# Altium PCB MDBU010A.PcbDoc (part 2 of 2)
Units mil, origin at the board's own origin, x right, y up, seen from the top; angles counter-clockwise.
Board outline 3300 x 2500 mil, 2 copper layers (Top Layer, Bottom Layer), stack 64.8 mil thick; 105 components, 70 nets, 307 pads, 460 vias.
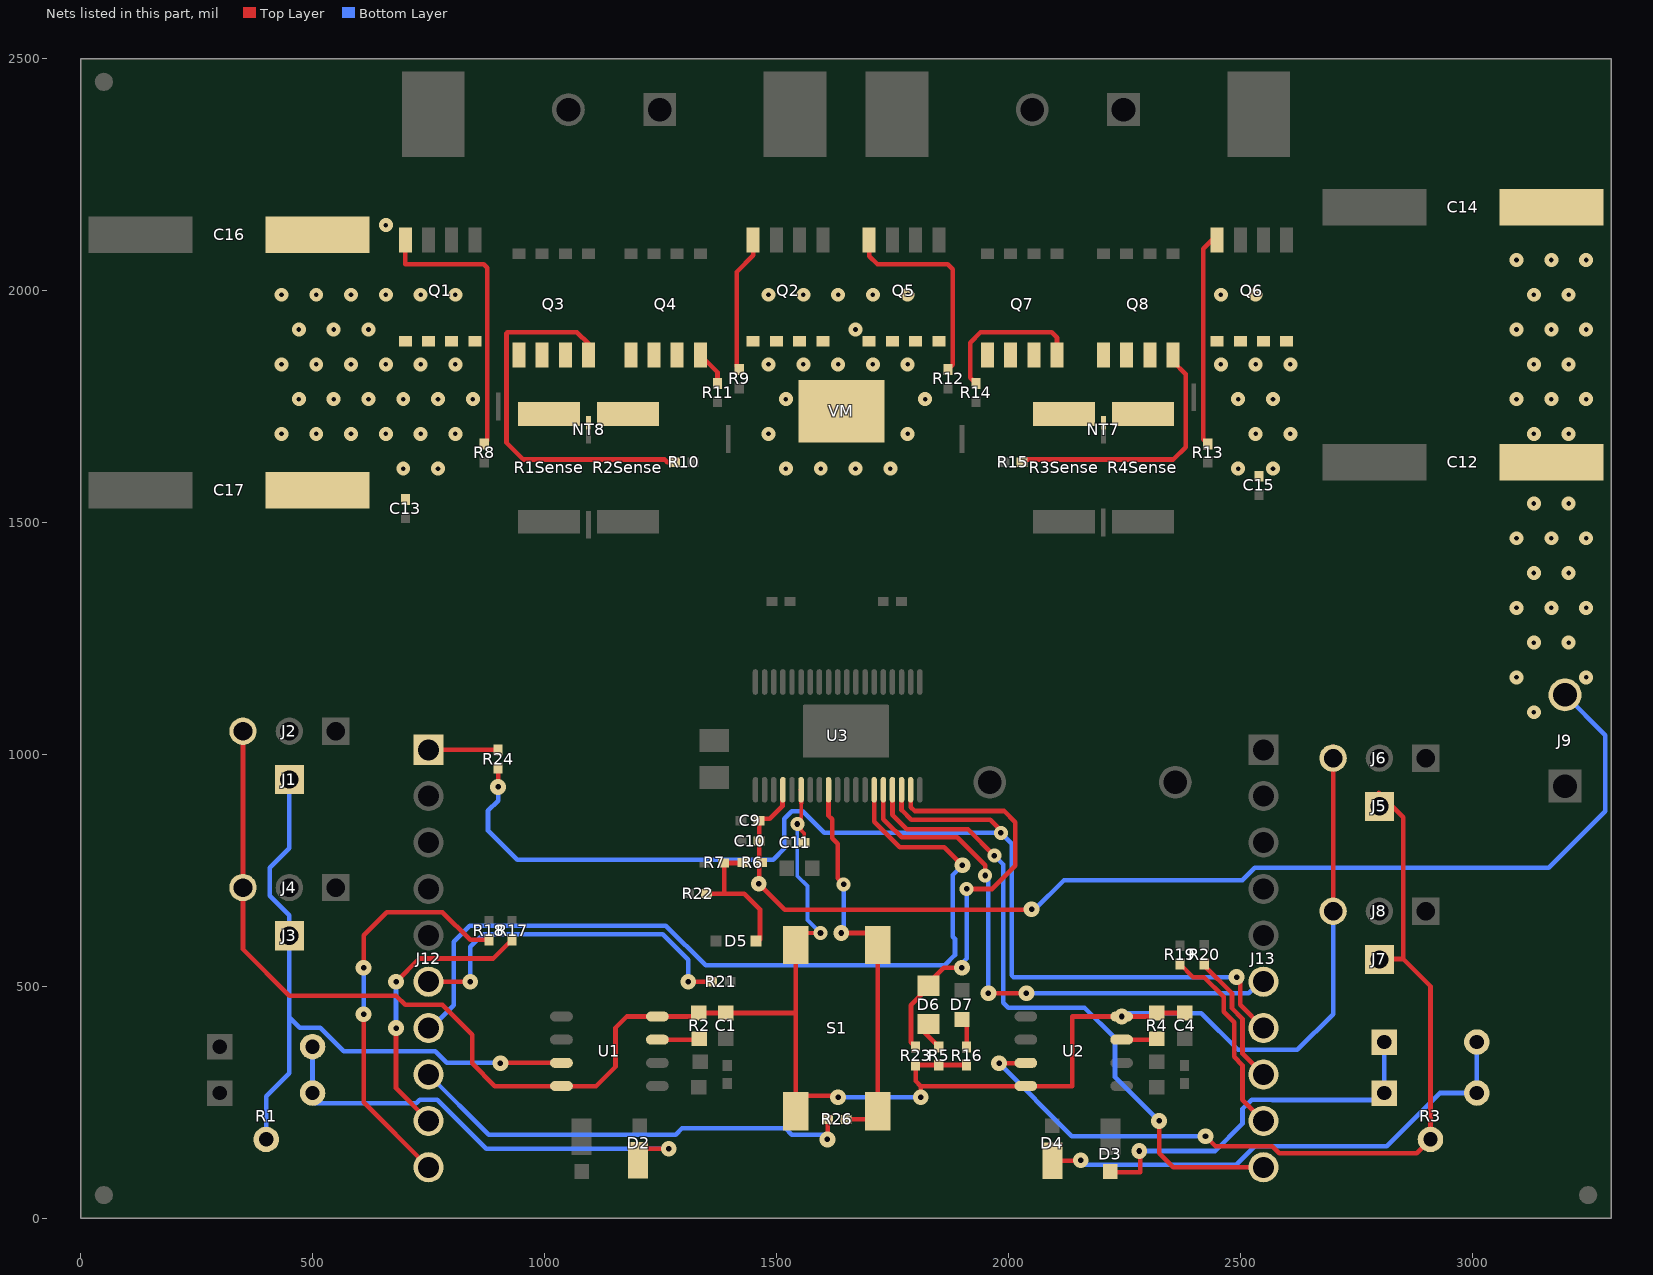
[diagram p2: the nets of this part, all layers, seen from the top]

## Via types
v1: diameter 30, hole 10, Top Layer to Bottom Layer, tented both sides, 357 vias
v2: diameter 34, hole 12, Top Layer to Bottom Layer, 60 vias
v3: diameter 34, hole 12, Top Layer to Bottom Layer, tented top, 20 vias
v4: diameter 20, hole 8, Top Layer to Bottom Layer, 12 vias
v5: diameter 30, hole 12, Top Layer to Bottom Layer, 11 vias

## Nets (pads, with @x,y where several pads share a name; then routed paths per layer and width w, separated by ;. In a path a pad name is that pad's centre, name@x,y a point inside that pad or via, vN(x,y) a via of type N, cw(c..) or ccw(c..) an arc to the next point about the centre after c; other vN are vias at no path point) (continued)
NetD2_1: D2.1 pad.1@500,370 R1.3 | length 978.7
  Top Layer w10: D2.1@1200,150 v2(1268,150)
  Bottom Layer w10: R1.3@500,270 pad.1@500,370 ; R1.3@504,248 723.86,248 731.21,255.35 768.79,255.35 874.14,150 v2(1268,150)
NetD3_2: D3.2 pad.0@2810,380 R3.1 | length 797.4
  Top Layer w10: D3.2@2220,100.79 2220,99 2284,99 v2@2284,143
  Bottom Layer w10: v2(2282,145) 2446,145 2504.65,203.65 2504.65,235.65 2524.35,255.35 2568.79,255.35 2569.14,255 R3.1@2795,255 ; R3.1@2810,270 pad.0@2810,380
NetD4_1: D4.1 pad.1@3010,380 R3.3 | length 1099.6
  Top Layer w10: D4.1@2095,124.41 2156,124.41 v2(2156,125)
  Bottom Layer w10: v2(2156,125) 2156,115.13 2490.99,115.13 2531.21,155.35 2815.35,155.35 2930,270 R3.3@3010,270 pad.1@3010,380
NetD5_1: D5.1 R6.1 R7.2 R22.2 | length 301.8
  Top Layer w10: R22.2@1349.69,700 1387.65,700 ; R6.1@1429.28,766 1387.65,766 1387.65,700 ; D5.1@1464.47,601 1464.47,666.56 1431.03,700 1387.65,700
NetD6_1: D6.1 R23.1 U3.18 | length 911.8
  Top Layer w10: U3.18@1789.48,923.86 1789.48,886.52 1798,878 1991,878 2015,854 2015,760 1965,710 v5(1910,710) ; R23.1@1800,369.68 1790,379.68 1790,459.53 D6.1@1820,489.53 ; D6.1@1815,494.53 1860.47,540 v2(1900,540)
  Bottom Layer w10: v2(1900,540) 1900,550 1910,560 v5(1910,710) v5@1909,709
NetD6_2: D6.2 R5.2 | length 73.2
  Top Layer w10: D6.2@1820,430.47 1820,399.69 R5.2@1850,369.69
NetD7_2: D7.2 R16.1 | length 48.8
  Top Layer w10: R16.1@1910,369.68 D7.2@1910,418.5
NetJ12_6: J12.6 R21.1 | length 767
  Top Layer w10: J12.6@750,510 v3(840,510) ; v2(1310,510) R21.1@1360.32,510
  Bottom Layer w10: v3(840,510) 840,584.94 867.71,612.64 1254.8,612.64 1310,557.44 v2(1310,510)
NetJ12_8: J12.8 R26.1 | length 958.1
  Top Layer w10: v2@1610.31,180.31 R26.1@1610.31,213.14
  Bottom Layer w10: J12.8@750,310 879.69,180.31 1282.89,180.31 1296.45,193.87 1519.55,193.87 1533.11,180.31 v2@1610.31,180.31
  other v2: 1610,170
NetJ12_9: J12.9 R17.1 | length 616.4
  Top Layer w10: v2(680,410) 680,280 J12.9@750,210 ; v2(680,510) 730,560 889.68,560 R17.1@930,600.32
  Bottom Layer w10: v2(680,410) v2(680,510)
NetJ12_10: J12.10 R18.1 | length 873.4
  Top Layer w10: v2(610,440) 610,250 J12.10@750,110 ; v2(610,540) 610,610 660,660 780,660 839.68,600.32 R18.1@880,600.32
  Bottom Layer w10: v2(610,440) v2(610,540)
NetJ13_8: J13.8 R20.1 | length 291.4
  Top Layer w10: R20.1@2422.28,548.49 2422.28,544.84 2482.13,485 2482.13,452.6 2504.65,430.08 2504.65,355.35 J13.8@2550,310
NetJ13_9: J13.9 R19.1 | length 426.6
  Top Layer w10: R19.1@2370,548.13 2398.13,520 2421.85,520 2464.25,477.6 2464.25,445.19 2486.77,422.67 2486.77,347.95 2504.65,330.08 2504.65,255.35 J13.9@2550,210
NetNT7_2: NT7.2 Q7.1 Q7.2 Q7.3 Q8.1 Q8.2 Q8.3 R3Sense.2 R4Sense.2
NetNT8_2: NT8.2 Q3.1 Q3.2 Q3.3 Q4.1 Q4.2 Q4.3 R1Sense.2 R2Sense.2
NetQ1_4: Q1.4 R8.2 | length 614.9
  Top Layer w10: Q1.4@700,2109.3 700,2056.43 869.31,2056.43 876.85,2048.89 876.85,1676.54 R8.2@870,1669.69
NetQ2_4: Q2.4 R9.1 | length 288.7
  Top Layer w10: R9.1@1414.26,1835.42 1414.26,2040 1450,2075.74 Q2.4@1450,2109.3
NetQ3_4: Q3.4 R10.2 | length 828.1
  Top Layer w10: Q3.4@1095,1860.7 1095,1885 1070,1910 920,1910 918.15,1908.15 918.15,1671.85 954.25,1635.75 1258.82,1635.75 1264.57,1630 R10.2@1280.31,1630
NetQ4_4: Q4.4 R11.1 | length 76.3
  Top Layer w10: Q4.4@1336,1860.7 1373,1823.7 R11.1@1373,1799.68
NetQ5_4: Q5.4 R12.2 | length 447
  Top Layer w10: Q5.4@1700,2109.3 1700,2074.3 1717.87,2056.43 1869.31,2056.43 1880,2045.74 1880,1839.69 R12.2@1870,1829.69
NetQ6_4: Q6.4 R13.1 | length 462.5
  Top Layer w10: R13.1@2430,1669.68 2420,1679.68 2420,2090 2439.3,2109.3 Q6.4@2450,2109.3
NetQ7_4: Q7.4 R14.2 | length 332.1
  Top Layer w10: R14.2@1930,1799.69 1917.87,1811.81 1917.87,1887.87 1940,1910 2093.57,1910 2105,1898.57 Q7.4@2105,1860.7
NetQ8_4: Q8.4 R15.1 | length 575.6
  Top Layer w10: R15.1@2029.68,1630 2035.43,1635.75 2355.75,1635.75 2382.13,1662.13 2382.13,1820 2355,1847.13 Q8.4@2355,1860.7
NetR2_1: R2.1 U1.7 | length 90
  Top Layer w10: U1.7@1243.35,385 R2.1@1333.32,385
NetR4_1: R4.1 U2.7 | length 73.2
  Top Layer w10: U2.7@2244.35,385 R4.1@2317.56,385
RESET: R26.2 S1.3 S1.4 U3.9 | length 793.6
  Top Layer w10: U3.9@1612.31,923.86 1612.31,867.79 1620.12,859.98 1620.12,819.23 1631.93,807.42 1631.93,733.07 v5(1645,720) ; v2(1640,615) 1710.43,615 1718.58,606.85 S1.4@1718.58,589.13 S1.3@1718.58,270.87 ; R26.2@1649.68,213.14 S1.3@1700.86,213.14
  Bottom Layer w10: v2(1640,615) 1645,620 v5(1645,720)
SCLK: J12.7 U3.14 | length 1853.6
  Top Layer w10: U3.14@1710.74,923.86 1710.74,855 1721.3,844.44 ; 1721.3,844.42 1765.72,800 1862,800 v2(1901,761)
  Bottom Layer w10: J12.7@750,410 755,410 804,459 804,596 839,631 1261.72,631 1347.47,545.25 1862.5,545.25 1884.87,567.63 1884.87,602.25 1880,607.12 1880,740 v2(1901,761)
SCS: J13.10 U3.16 | length 1417
  Top Layer w10: U3.16@1750.11,923.86 1750.11,869.89 1781,839 1913,839 v5(1970,782) ; v3(2325,210) 2325,140.13 2355.13,110 J13.10@2550,110
  Bottom Layer w10: v5(1970,782) 1989.25,762.75 1989.25,464.47 1999.72,454 2164.12,454 2230,388.12 2230,304 v3@2313,221
SDATI: J13.6 U3.15 | length 1206.4
  Top Layer w10: U3.15@1730.43,923.86 1730.43,860.59 1739.17,851.84 1769.87,821.13 1889.87,821.13 1950,761 v5(1950,739) ; v3(1957,485) v3(2039,485)
  Bottom Layer w10: v5(1950,739) 1957,732 v3(1957,485) ; v3(2039,485) 2518.01,485 2543.01,510 J13.6@2550,510
SDATO: J13.7 R24.1 U3.17 | length 2595.8
  Top Layer w10: v2(900,930) R24.1@900,970.32 ; U3.17@1769.8,923.86 1769.8,880.2 1791,859 1961,859 v5@1990,830 ; v2@2496,520 2500,516 2500,460 J13.7@2550,410
  Bottom Layer w10: v2(900,930) 900,900.25 878.13,878.37 878.13,836.13 941.02,773.23 1493.23,773.23 1517.13,797.13 1517.13,861.55 1533.45,877.87 1556.55,877.87 1603.42,831 v5(1984,831) 2007.13,807.87 2007.13,524 2011.13,520 v2(2492,520)
TLC555_OUT_1: J1.1 J3.1 R1.2 U1.3 | length 1459.1
  Top Layer w10: v2@906,335 U1.3@1036.65,335
  Bottom Layer w10: R1.2@400,170 400,263 450,313 450,433 ; J1.1@450,947 450,797.8 407.6,755.4 407.6,695.44 450,653.04 450,610 450,433 ; v2@905,335 789.14,335 764.14,360 567.1,360 516.72,410.37 472.63,410.37 450,433
  other v2: 905,334
TLC555_OUT_2: J5.1 J7.1 R3.2 U2.3 | length 1923.7
  Top Layer w10: v2(1980,334) U2.3@2036.65,334 ; v2(2425,177) 2446.65,155.35 2568.79,155.35 2584.14,140 2880,140 R3.2@2910,170 2910,500 2851.02,558.98 ; J5.1@2798.16,917.01 2851.02,864.15 2851.02,558.98 ; J7.1@2800.05,558.98 2851.02,558.98
  Bottom Layer w10: v2(1980,334) 2137,177 v2(2425,177)
V3.3: J12.1 R24.2 | length 149.7
  Top Layer w10: J12.1@750,1010 R24.2@899.69,1010
V5: C1.2 C4.2 C11.1 J2.3 J4.3 J6.3 J8.3 R2.2 R4.2 R5.1 R16.2 R23.2 S1.1 S1.2 U1.4 U1.8 U2.4 U2.8 U3.6 | length 4947.2
  Top Layer w8: S1.2@1541.42,589.13 1567.28,615 v5(1595,615) ; 1553.26,895.33 1553.26,836.43 1559.68,830 C11.1@1559.68,810
  Top Layer w10: J2.3@350,1050 J4.3@350,713 350,580 449.87,480.13 679.87,480.13 700,460 780,460 844,396 844,334 893,285 U1.4@1036.65,285 1111,285 1153.13,327.13 1153.13,411.13 1177,435 U1.8@1243.35,435 R2.2@1333,435 ; R2.2@1333,442.56 C1.2@1391,442.56 1541.42,442.56 ; S1.1@1541.42,270.87 1541.42,442.56 ; S1.2@1541.42,589.13 1541.42,442.56 ; S1.1@1548.28,264 v3@1630,264 ; U3.6@1552.94,923.54 U3.6@1553.26,923.86 1553.26,895.33 ; v2@1810,260 v2(1811,261) 1811,285 ; R16.2@1910,330.31 R5.1@1850,330.32 R23.2@1800,330.31 1800,296 1811,285 ; C4.2@2380,442.56 R4.2@2320,442.56 2312.44,435 v2(2244.35,435) 2138,435 2138,285 U2.4@2037.65,285 1811,285 ; J8.3@2700.05,661.98 J6.3@2700.05,1016
  Bottom Layer w8: v5(1545,850) 1545,738.01 1566.87,716.13 1566.87,643.13 v5(1595,615)
  Bottom Layer w10: v3@1630,264 v3(1633,261) v2(1811,261) ; v2@2251.35,442 2416,442 2495,363 2623,363 2700.05,440.05 J8.3@2700.05,661.98
VM: C9.2 C10.2 C12.1 C13.1 C14.1 C15.1 C16.1 C17.1 J9.2 Q1.5 Q1.6 Q1.7 Q1.8 Q2.5 Q2.6 Q2.7 Q2.8 Q5.5 Q5.6 Q5.7 Q5.8 Q6.5 Q6.6 Q6.7 Q6.8 R6.2 U3.4 VM.1 | length 2442.7
  Top Layer w10: v2(1462,721) 1518,665 v2@2035,665 ; v2@1462.69,721.69 C10.2@1462.69,813 C9.2@1462.69,857 1466.69,861 1485.65,861 1512.98,888.33 1512.98,922.95 U3.4@1513.89,923.86
  Bottom Layer w10: v2(2050,666) 2057.21,666 2120,728.79 2504.65,728.79 2531.21,755.35 3165.35,755.35 3287.13,877.13 3287.13,1041.3 J9.2@3200,1128.43
  other v1: 3133,1091 3095.5,1166 3245.5,1166 3133,1241 3208,1241 3095.5,1316 3170.5,1316 3245.5,1316 3133,1391 3208,1391 3095.5,1466 3170.5,1466 3245.5,1466 3133,1541 3208,1541 695.5,1616 770.5,1616 1520.5,1616 1595.5,1616 1670.5,1616 1745.5,1616 2495.5,1616 2570.5,1616 433,1691 508,1691 583,1691 658,1691 733,1691 808,1691 1483,1691 1783,1691 2533,1691 2608,1691 3133,1691 3208,1691 470.5,1766 545.5,1766 620.5,1766 695.5,1766 770.5,1766 845.5,1766 1520.5,1766 1820.5,1766 2495.5,1766 2570.5,1766 3095.5,1766 3170.5,1766 3245.5,1766 433,1841 508,1841 583,1841 658,1841 733,1841 808,1841 1483,1841 1558,1841 1633,1841 1708,1841 1783,1841 2458,1841 2533,1841 2608,1841 3133,1841 3208,1841 470.5,1916 545.5,1916 620.5,1916 1670.5,1916 3095.5,1916 3170.5,1916 3245.5,1916 433,1991 508,1991 583,1991 658,1991 733,1991 808,1991 1483,1991 1558,1991 1633,1991 1708,1991 1783,1991 2458,1991 2533,1991 3133,1991 3208,1991 3095.5,2066 3170.5,2066 3245.5,2066 658,2141
pads on no net: FID1.1 FID2.1 FID3.1 J12.2 J12.3 J12.4 J12.5 J13.2 J13.3 J13.4 J13.5 U3.20

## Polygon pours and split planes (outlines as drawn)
GND on Top Layer "Top Layer-No Net" (solid, remove dead copper, pour order 17): 20,20 20,2480 3280,2480 3280,20 20,20
VM on Top Layer "VM" (solid, remove dead copper, pour order 26): 2420,1900 2420,1590 2630,1590 2630,1900 2420,1900
VM on Top Layer "VM" (solid, remove dead copper, pour order 24): 1430,2040 1430,1590 1865,1590 1865,2040
VM on Top Layer "VM" (solid, remove dead copper, pour order 23): 3060,2250 3060,1040 3280,1040 3280,2250 3060,2250
VM on Top Layer "VM" (solid, remove dead copper, pour order 21): 400,2480 685,2480 685,2050 863.98,2050 863.98,1530 860,1530 400,1530 400,2479.68
MA1 on Top Layer "MA1" (solid, remove dead copper, pour order 22): 1120,2480 685,2480 685,1930 1120,1930
MA2 on Top Layer "MA2" (solid, remove dead copper, pour order 19): 1160,2480 1615,2480 1615,1930 1160,1930
MB1 on Top Layer "MB1" (solid, remove dead copper, pour order 18): 2140,2480 1685,2480 1685,1930 2140,1930
MB2 on Top Layer "MB2" (solid, remove dead copper, pour order 15): 2180,2480 2615,2480 2615,1930 2180,1930
NetNT8_2 on Top Layer "AISENP" (solid, remove dead copper, pour order 27): 926.54,1892.43 926.54,1662.43 1366,1662.43 1366,1892.43 926.54,1892.43
NetNT7_2 on Top Layer "BISENP" (solid, remove dead copper, pour order 25): 1938,1892.13 1938,1662.13 2378,1662.13 2378,1892.13 1938,1892.13
GND on Bottom Layer "GND" (solid, remove dead copper, pour order 20): 20,20 20,2480 3280,2480 3280,20 20,20
VM on Bottom Layer "VM" (solid, remove dead copper, pour order 16): 3060,2250 3280,2250 3280,1040 3060,1040 3060,2250
VM on Bottom Layer "VM" (solid, remove dead copper, pour order 28): 400,2250 400,1590 3280,1590 3280,2250

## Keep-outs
Keep-Out Layer:
  lines w10: -5,0 ccw(c0,0) 0,-5 ; -5,0 ccw(c0,0) 0,-5 ; -5,0 ccw(c0,0) 0,-5 ; -5,0 ccw(c0,0) 0,-5 ; -5,0 -5,2500 ; -5,2500 cw(c0,2500) 0,2505 ; -5,2500 cw(c0,2500) 0,2505 ; 0,-5 3300,-5 ; 0,-5 3300,-5 ; 0,2505 3300,2505 ; 3300,-5 ccw(c3300,0) 3305,0 ; 3300,-5 ccw(c3300,0) 3305,0 ; 3300,-5 ccw(c3300,0) 3305,0 ; 3300,-5 ccw(c3300,0) 3305,0 ; 3300,2505 cw(c3300,2500) 3305,2500 ; 3300,2505 cw(c3300,2500) 3305,2500 ; 3305,0 3305,2500
  text ".Layer_Name" at 577,-858.49 h60

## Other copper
Top Layer:
  rectangle net GND: 1804,895 2074,1017
  rectangle net GND: 1536,997 1639,1051
  text ".Layer_Name" at 577,-858.49 h60
Bottom Layer:
  text ".Layer_Name" at 577,-858.49 h60

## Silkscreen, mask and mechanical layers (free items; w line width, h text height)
Top Overlay:
  lines w3: 802,507 885,507
  lines w4: 1756,420 1756,532
  lines w5: 1265,1560 2035,1560 ; 1270,1370 1270,1300 1320,1250 ; 1320,1370 1320,1320 1350,1290 ; 1370,1370 1370,1350 1400,1320 ; 1420,1370 1420,1350 1455,1315 ; 1470,1370 1470,1350 1473,1347 ; 1508,1312 1525,1295 ; 1520,1370 1520,1350 1522,1348 ; 1570,1325 1590,1310 1590,1296 ; 1570,1365 1570,1370 ; 1619.87,1326 1619.87,1369.87 ; 1650,1296 1650,1310 1670,1325 ; 1670,1365 1670,1370 ; 1695,1325 1710,1340 ; 1710,1296 1710,1300 1712,1302 ; 1720,1350 1720,1370 ; 1760,1350 1770,1360 1770,1370 ; 1780,1297.88 1822.12,1340 1840,1340 1870,1370 ; 1790,1340 1820,1370 ; 1848,1300 1850,1300 1920,1370 ; 1890,1290 1970,1370 ; 1910,1256 1910,1260 2020,1370
  lines w10: 180,830 702,830 ; 2600,770 3045.35,770
  text "MA1" at 690,2180 h100
  text "MA2" at 1430,2180 h100
  text "MB1" at 1690,2180 h100
  text "MB2" at 2430,2180 h100
  text "Motor A" at 990,2110 h100
  text "Motor B" at 2000,2110 h100
  text "Test Point Vias" at 1520,1570 h40
  text "AOUT1" at 1290,1380 h50 r90
  text "A1HS" at 1340,1380 h50 r90
  text "A1LS" at 1390,1380 h52 r90
  text "AISENP" at 1440,1380 h50 r90
  text "AISENN" at 1490,1380 h50 r90
  text "A2LS" at 1540,1380 h50 r90
  text "A2HS" at 1590,1380 h50 r90
  text "AOUT2" at 1640,1380 h50 r90
  text "BOUT1" at 1690,1380 h50 r90
  text "B1HS" at 1740,1380 h50 r90
  text "B1LS" at 1790,1380 h50 r90
  text "BISENP" at 1840,1380 h50 r90
  text "BISENN" at 1890,1380 h50 r90
  text "B2LS" at 1940,1380 h50 r90
  text "B2HS" at 1990,1380 h50 r90
  text "BOUT2" at 2040,1380 h50 r90
  text "VM" at 3160,1260 h60
  text ".PRJ_Number" at 2430,1210 h60
  text ".PCB_Rev" at 2700,1210 h60
  text "AIN1" at 400,1120 h50
  text "BIN1" at 2750,1060 h50
  text "HIGH" at 180,1050 h50
  text "LOW" at 610,1050 h50
  text "HIGH" at 2598,1050 h50
  text "LOW" at 2900,1050 h50
  text "DRV8704EVM" at 1890,1020 h60
  text "VCC" at 798,980 h30
  text "GND" at 2450,980 h30
  text "GND" at 2300,860 h60
  text "PWM" at 400,850 h50
  text "PWM" at 2750,790 h50
  text "AIN2" at 400,770 h50
  text "GND" at 3140,740 h60
  text "BIN2" at 2750.05,725.11 h50
  text "HIGH" at 2598,720 h50
  text "LOW" at 2900,720 h50
  text "HIGH" at 180,710 h50
  text "LOW" at 610,710 h50
  text "PWM" at 2870,530 h50
  text "PWM" at 400,520 h50
  text "SLEEP" at 800,480 h30
  text "SDATI" at 2400,480 h30
  text "FAULT" at 1790,419.61 h40 r90
  text "STATUS" at 1953.32,415 h40 r90
  text "SCLK" at 800,380 h30
  text "SDATO" at 2410,380 h30
  text "RESET" at 800,280 h30
  text "BIN1" at 2450,280 h30
  text "BIN2" at 2449.52,181.22 h30
  text "AIN1" at 800,180 h30
  text "SPEED" at 3130,150 h50
  text "SPEED" at 40,100 h50
  text "RESET" at 1516,90 h80
  text "AIN2" at 800,80 h30
  text "SCS" at 2450,80 h30
  text "Motor A Control" at 170,20 h80
  text "Motor B Control" at 2660,20 h80
  text ".Layer_Name" at 577,-858.49 h60
Bottom Overlay:
  text ".Layer_Name" at 577,-858.49 h60
Top Paste:
  text ".Layer_Name" at 577,-858.49 h60
Bottom Paste:
  text ".Layer_Name" at 577,-858.49 h60
Top Solder:
  text ".Layer_Name" at 577,-858.49 h60
  text ".Layer_Name" at 577,-858.49 h60
Bottom Solder:
  text ".Layer_Name" at 577,-858.49 h60
Drill Guide:
  text ".Layer_Name" at 577,-858.49 h60
M1 Board Outline:
  the board outline again, w10
  text ".Layer_Name" at 577,-858.49 h60
M2 Board Dimensions:
  rectangle: 125,-400 500,-275
  rectangle: 0,-275 125,-150
  lines w7: 0,-275 1000,-275 ; 125,-400 125,-150 ; 250,-400 250,-150 ; 500,-400 500,-150 ; 750,-400 750,-150 ; 0,-400 0,-150 1000,-150 1000,-400 0,-400
  lines w10: -100,0 0,0 0,-100 ; -100,2500 0,2500 ; -70,60 -50,0 ; -70,2440 -50,2500 ; -50,969.09 -50,0 ; -50,1530.91 -50,2500 ; -30,60 -50,0 ; -30,2440 -50,2500 ; 60,-70 0,-50 ; 60,-30 0,-50 ; 1369.09,-50 0,-50 ; 1930.91,-50 3300,-50 ; 3240,-70 3300,-50 ; 3240,-30 3300,-50 ; 3300,-100 3300,0
  text "2500 (mil)" at -14.01,979.09 h60 r90
  text "3300 (mil)" at 1379.09,-85.99 h60
  text ".Layer_Name" at 577,-858.49 h60
M3 3D STEP Top:
  text ".Layer_Name" at 577,-858.49 h60
M4 3D STEP Bottom:
  text ".Layer_Name" at 577,-858.49 h60
M5 Assembly Top:
  lines w10: -292,-930.17 6308,-930.17 ; -292,-726.83 6310,-726.83 ; -292,-523.5 -292,-1133.5 3713,-1133.5 6310,-1133.5 6310,-523.5 -291.5,-523.5 -291.5,-1133.5 1284,-1133.5 ; 2173,-1133.5 2173,-523.5 ; 3440,-726.83 3440,-523.5 ; 4280,-726.83 4280,-523.5 ; 4902,-1140 4902,-937.17
  text "COMPONENTS MARKED 'DNP' SHOULD NOT BE POPULATED." at 1153.5,-318.5 h60
  text "ASSEMBLY VARIANT:" at 1153,-434 h60
  text ".VariantName" at 2189,-434 h60
  text "PCB VIEWED FROM TOP SIDE" at -228.5,-655.67 h60
  text "BOARD #:" at 2248,-655.67 h60
  text ".PRJ_Number" at 2793.5,-655.67 h60
  text "REV:" at 3638,-655.67 h60
  text ".PCB_Rev" at 3929.5,-655.67 h60
  text "SVN REV:" at 4476,-655.67 h60
  text ".VersionControl_RevNumber" at 4982,-655.67 h60
  text "TID #:" at 2248,-859 h60
  text ".TID" at 2793.5,-859 h60
  text "PLOT NAME =" at -228.5,-1064.34 h60
  text ".plot_File_Name" at 577,-1064.34 h60
  text "GENERATED    :" at 2250,-1064.34 h60
  text ".Print_Date" at 3119.5,-1064.34 h60
  text ".Print_Time" at 3848.5,-1064.34 h60
  text "TEXAS INSTRUMENTS" at 5113,-1064.34 h60
M6 Assembly Bottom:
  lines w10: -292.5,-727.33 6309.5,-727.33 ; -290.5,-930.67 6309.5,-930.67 ; 1115.5,-1140.5 1115.5,-937.67 ; 1737.5,-727.33 1737.5,-524 ; 2577.5,-727.33 2577.5,-524 ; 3844.5,-1134 3844.5,-524 ; 4733.5,-1134 6309,-1134 6309,-524 -292.5,-524 -292.5,-1134 2304.5,-1134 6309.5,-1134 6309.5,-524
  text "COMPONENTS MARKED 'DNP' SHOULD NOT BE POPULATED." at 6102,-318 h60
  text ".VariantName" at 5058,-434 h60
  text "ASSEMBLY VARIANT:" at 6097,-434 h60
  text ".VersionControl_RevNumber" at 1035.5,-656.17 h60
  text "SVN REV:" at 1541.5,-656.17 h60
  text ".PCB_Rev" at 2088,-656.17 h60
  text "REV:" at 2379.5,-656.17 h60
  text ".PRJ_Number" at 3224,-656.17 h60
  text "BOARD #:" at 3769.5,-656.17 h60
  text "PCB VIEWED FROM BOTTOM SIDE" at 6246,-656.17 h60
  text ".TID" at 3224,-859.5 h60
  text "TID #:" at 3769.5,-859.5 h60
  text "TEXAS INSTRUMENTS" at 904.5,-1064.84 h60
  text ".Print_Time" at 2169,-1064.84 h60
  text ".Print_Date" at 2898,-1064.84 h60
  text "GENERATED    :" at 3767.5,-1064.84 h60
  text ".plot_File_Name" at 5440.5,-1064.84 h60
  text "PLOT NAME =" at 6246,-1064.84 h60
M9 Title Sheet:
  drawing of 57 lines, arcs and shapes, not listed
  text "1" at 739.84,8036.5 h70
  text "2" at 3235.5,8036.5 h70
  text "3" at 5724.84,8036.5 h70
  text "4" at 8231.51,8036.5 h70
  text "5" at 10730.5,8036.5 h70
  text "6" at 13235.5,8036.5 h70
  text "A" at -416.5,6893.5 h70
  text "A" at 14383.5,6893.5 h70
  text "B" at -416.5,4513.5 h70
  text "B" at 14383.5,4513.5 h70
  text "C" at -416.5,2138.5 h70
  text "C" at 14383.5,2138.5 h70
  text "PROJECT TITLE:" at 11343.5,277.5 h45
  text ".PRJ_Title" at 11393.5,144.17 h70
  text "DESIGNED FOR:" at 11343.5,-23.5 h45
  text ".PRJ_Customer" at 11393.5,-163.5 h70
  text "D" at -416.5,-231.5 h70
  text "D" at 14383.5,-231.5 h70
  text "FILE NAME:" at 11343.5,-323.5 h45
  text ".PCB_File_Name_No_Path" at 11393.5,-443.5 h70
  text "Texas Instruments (TI) and/or its licensors do not warrant the accuracy or completeness of this specification" at 6374,-605.34 h45
  text "ENGINEER:" at 11343.5,-613.5 h45
  text "LAYOUT BY:" at 12848.5,-613.5 h45
  text "or any information contained therein. TI and/or its licensors do not warrant that this design will meet" at 6329.01,-718 h45
  text ".PRJ_Engineer" at 11393.5,-768.49 h70
  text ".PCB_Layout" at 12899,-768.49 h70
  text "the specifications, will be suitable for your application or fit for any particular purpose, or will operate in" at 6329.01,-830.67 h45
  text ".Layer_Name" at 577,-858.49 h60
  text "ALTIUM DESIGNER VERSION:" at 12848.5,-923.5 h45
  text "an implementation. TI and/or its licensors do not warrant that the design is production worthy. You should" at 6329.01,-943.33 h45
  text "completely validate and test your design implementation to confirm the system functionality for your application." at 6374,-1056 h45
  text ".print_Scale" at 11393.5,-1056.83 h70
  text ".Application_BuildNumber" at 12899,-1056.83 h70
  text "1" at 739.84,-1263.5 h70
  text "2" at 3235.5,-1263.5 h70
  text "3" at 5724.84,-1263.5 h70
  text "4" at 8231.51,-1263.5 h70
  text "5" at 10730.5,-1263.5 h70
  text "6" at 13235.5,-1263.5 h70
M10 Fab Notes:
  drawing of 185 lines, arcs and shapes, not listed
  text "DESIGN INFORMATION" at 12381.02,5910 h60
  text "MIN. TRACK WIDTH:" at 11736.46,5730 h60
  text "8" at 12832.7,5730 h60
  text "MIL" at 12987.46,5730 h60
  text "MIN. CLEARANCE:" at 11736.46,5598 h60
  text "0.2" at 12772.7,5598 h60
  text "mm" at 12987.46,5598 h60
  text "MIN. VIA PAD SIZE:" at 11736.46,5466 h60
  text "24" at 12802.71,5466 h60
  text "MIL" at 12987.46,5466 h60
  text "0.05mm (2MIL)" at 12431.46,5324.29 h60
  text "MINIMUM ANNULAR RING" at 11407.23,5320 h60
  text "EXTERNAL" at 13139.46,5320 h60
  text "PER" at 11607.23,5202 h60
  text "IPC-D-275 CLASS 2 LEVEL C" at 11827.23,5202 h60
  text "MIL, HOLES" at 13315.46,5089.71 h60
  text "+/-" at 12923,5089 h60
  text "+/-" at 13777,5089 h60
  text "REGISTRATION TOLERANCES:" at 11407.23,5084 h60
  text "METAL" at 12607,5084 h60
  text "5" at 13183.2,5084 h60
  text "3" at 14016.2,5084 h60
  text "MIL" at 14132.46,5084 h60
  text "MATERIAL:" at 11332.46,4874.54 h60
  text "FR-4 High Tg" at 12318.9,4734.21 h60
  text "FR-408" at 11753.46,4725.64 h60
  text "X" at 12165.46,4725.64 h60
  text "OTHER" at 13241.46,4725.64 h60
  text "62 MIL (1.6mm) +/-10%" at 12073.56,4562.92 h60
  text "THICKNESS:" at 11407.23,4558.64 h60
  text "X" at 11945.4,4558.64 h60
  text "OTHER" at 13358.46,4558.64 h60
  text "TOLERANCE:" at 11407.23,4400.64 h60
  text "X" at 12246.53,4400.64 h60
  text "ANSI IPC-6012 TYPE 3 CLASS 2" at 12433.48,4400.64 h60
  text "OTHER +/-" at 12433.46,4244.64 h60
  text "BOW & TWIST:" at 11407.23,4087.64 h60
  text "X" at 12246.53,4087.64 h60
  text "ANSI IPC-6012 TYPE 3 CLASS 2" at 12433.48,4087.64 h60
  text "OTHER +/-" at 12433.46,3929.13 h60
  text "DRILLING:" at 11332.46,3790.64 h60
  text "REFERENCE:" at 11407.23,3673.64 h60
  text "X" at 12055.46,3673.64 h60
  text "AS SHOWN" at 12242.46,3673.64 h60
  text "X" at 12956.46,3673.64 h60
  text "NC_DRILL FILES" at 13093.46,3673.64 h60
  text "PTH MIN COPPER THICKNESS:" at 11407.23,3515.64 h60
  text "1MIL" at 12894.46,3515.64 h60
  text "OTHER" at 13391.46,3515.64 h60
  text "X" at 12760,3510 h60
  text "BOARD FINISH:" at 11332.46,3356.64 h60
  text "SILKSCREEN:" at 11487.68,3238.64 h60
  text "X" at 12436.46,3238.64 h60
  text "TOP" at 12562.46,3238.64 h60
  text "BOTTOM" at 13073.46,3238.64 h60
  text "SILKSCREEN COLOR:" at 11487.68,3071.64 h60
  text "X" at 12435.42,3071.64 h60
  text "WHITE" at 12562.46,3071.64 h60
  text "OTHER" at 13073.46,3071.64 h60
  text "SOLDER RESIST COLOR:" at 11487.68,2901.64 h60
  text "X" at 12055.42,2742.44 h60
  text "GREEN" at 12182.46,2742.44 h60
  text "BLUE" at 12773.46,2742.44 h60
  text "OTHER" at 13311.46,2742.44 h60
  text "IMMERSION GOLD (ENIG)" at 12393.46,2553.92 h60
  text "ENEPIG" at 13731,2550.64 h60
  text "SURFACE FINISH:" at 11332.46,2549.64 h60
  text "X" at 12206.51,2549.64 h60
  text "IMM. TIN/SILVER OR EQUIV" at 11662,2392.64 h60
  text "OTHER" at 13093.46,2392.64 h60
  text "ARRAY/PANEL:" at 11332.46,2213.64 h60
  text "CUT AND TRIM PER MECH LAYER 1" at 12393.46,2209.35 h60
  text "N.C. ROUTE" at 12393.46,2057.64 h60
  text "X" at 13072.46,2057.64 h60
  text "V. SCORE" at 13259.46,2057.64 h60
  text "CERTIFICATION:" at 11332.46,1920.64 h60
  text "MATERIALS AND WORKMANSHIP FOR ALL PCBS" at 12057.46,1920.64 h60
  text "TO MEET OR EXCEED THE REQUIREMENTS OF:" at 12057.46,1822.64 h60
  text "X" at 11683.96,1686.13 h60
  text "ANSI IPC-A-600F CLASS ->" at 11822.96,1686.13 h60
  text "X" at 13462.02,1686.13 h60
  text "2" at 13580.96,1686.14 h60
  text "1" at 13265.96,1684.64 h60
  text "3" at 13934.96,1684.64 h60
  text "X" at 11686.02,1526.64 h60
  text "UL 94V-0" at 11822.96,1526.64 h60
  text "X" at 12498.02,1526.64 h60
  text "RoHS" at 12634.96,1526.64 h60
  text "OTHER" at 13279.36,1526.64 h60
  text "PER ORDER" at 13676.42,1526.64 h60
  text "ADDITIONAL REQUIREMENTS:" at 11332.46,1385.64 h60
  text "MICROSECTION:" at 11407.23,1270.64 h60
  text "YES" at 12312.96,1270.64 h60
  text "REQUIRED" at 13174.46,1114.49 h60
  text "BARE BOARD ELEC. TEST:" at 11407.23,1111.64 h60
  text "NONE" at 12712.96,1111.64 h60
  text "X" at 13047.46,1111.64 h60
  text "PER ORDER" at 13766.46,1111.64 h60
  text "MANUFACTURER'S UL:" at 11407.23,954.64 h60
  text "RAIL" at 12572.96,950.35 h60
  text "METAL" at 13064.77,950.35 h60
  text "X" at 13440,950 h60
  text "SILK" at 13576.46,950.35 h60
  text ".Layer_Name" at 577,-858.49 h60
M11 Gerber Information:
  lines w10: -292,-930.17 6308,-930.17 ; -292,-726.83 6310,-726.83 ; -292,-523.5 -292,-1133.5 3713,-1133.5 6310,-1133.5 6310,-523.5 -291.5,-523.5 -291.5,-1133.5 1284,-1133.5 ; 2173,-1133.5 2173,-523.5 ; 3440,-726.83 3440,-523.5 ; 4280,-726.83 4280,-523.5 ; 4902,-1140 4902,-937.17
  text "ALL ARTWORK VIEWED FROM TOP SIDE" at -228.5,-655.67 h60
  text "BOARD #:" at 2248,-655.67 h60
  text ".PRJ_Number" at 2793.5,-655.67 h60
  text "REV:" at 3638,-655.67 h60
  text ".PCB_Rev" at 3929.5,-655.67 h60
  text "SVN REV:" at 4476,-655.67 h60
  text ".VersionControl_RevNumber" at 4982,-655.67 h60
  text "LAYER NAME =" at -228.5,-858.49 h60
  text "TID #:" at 2248,-859 h60
  text ".TID" at 2793.5,-859 h60
  text "PLOT NAME =" at -228.5,-1064.34 h60
  text ".plot_File_Name" at 577,-1064.34 h60
  text "GENERATED    :" at 2250,-1064.34 h60
  text ".Print_Date" at 3119.5,-1064.34 h60
  text ".Print_Time" at 3848.5,-1064.34 h60
  text "TEXAS INSTRUMENTS" at 5113,-1064.34 h60
M12 Stackup:
  drawing of 165 lines, arcs and shapes, not listed
  text "Layer" at 9790.58,7830 h60
  text "Name" at 10200.49,7830 h60
  text "Material" at 11060.26,7830 h60
  text "Thickness" at 11920.02,7830 h60
  text "Constant" at 12569.86,7830 h60
  text "Board Layer Stack" at 13139.72,7830 h60
  text "1" at 9790.58,7710 h60
  text "Top Overlay" at 10200.49,7710 h60
  text "2" at 9790.58,7590 h60
  text "Top Solder" at 10200.49,7590 h60
  text "Solder Resist" at 11060.26,7590 h60
  text "0.40mil" at 11920.02,7590 h60
  text "3.5" at 12569.86,7590 h60
  text "3" at 9790.58,7470 h60
  text "Top Layer" at 10200.49,7470 h60
  text "Copper" at 11060.26,7470 h60
  text "2.80mil" at 11920.02,7470 h60
  text "4" at 9790.58,7350 h60
  text "Dielectric1" at 10200.49,7350 h60
  text "FR-4" at 11060.26,7350 h60
  text "59.20mil" at 11920.02,7350 h60
  text "4.8" at 12569.86,7350 h60
  text "5" at 9790.58,7230 h60
  text "Bottom Layer" at 10200.49,7230 h60
  text "Copper" at 11060.26,7230 h60
  text "2.80mil" at 11920.02,7230 h60
  text "6" at 9790.58,7110 h60
  text "Bottom Solder" at 10200.49,7110 h60
  text "Solder Resist" at 11060.26,7110 h60
  text "0.40mil" at 11920.02,7110 h60
  text "3.5" at 12569.86,7110 h60
  text ".Layer_Name" at 577,-858.49 h60
M13 Component Bodies Top:
  text ".Layer_Name" at 577,-858.49 h60
M14 Component Bodies Bottom:
  text ".Layer_Name" at 577,-858.49 h60
M15 Courtyards Top:
  text ".Layer_Name" at 577,-858.49 h60
M16 Courtyards Bottom:
  text ".Layer_Name" at 577,-858.49 h60
Drill Drawing:
  circle w1: c4092.72,1375.12 r14.93
  circle w1: c4092.72,1375.12 r24.89
  circle w1: c4092.72,1225.8 r24.89
  lines w1: 4067.83,1512 4080.27,1512 4080.27,1499.56 4105.16,1499.56 4105.16,1512 4117.6,1512 4117.6,1536.89 4105.16,1536.89 4105.16,1549.33 4080.27,1549.33 4080.27,1536.89 4067.83,1536.89 4067.83,1512 ; 4067.83,1648.88 4067.83,1661.32 4080.27,1673.76 4067.83,1686.21 4067.83,1698.65 4080.27,1698.65 4092.72,1686.21 4105.16,1698.65 4117.6,1698.65 4117.6,1686.21 4105.16,1673.76 4117.6,1661.32 4117.6,1648.88 4105.16,1648.88 4092.72,1661.32 4080.27,1648.88 4067.83,1648.88 ; 4067.83,1810.64 4080.27,1810.64 4092.72,1798.2 4105.16,1810.64 4117.6,1810.64 4105.16,1823.08 4117.6,1835.53 4105.16,1835.53 4092.72,1847.97 4080.27,1835.53 4067.83,1835.53 4080.27,1823.08 4067.83,1810.64 ; 4067.83,1959.96 4080.27,1959.96 4092.72,1947.52 4105.16,1959.96 4117.6,1959.96 4105.16,1972.4 4117.6,1984.85 4105.16,1984.85 4092.72,1997.29 4080.27,1984.85 4067.83,1984.85 4080.27,1972.4 4067.83,1959.96 ; 4067.83,2096.84 4092.72,2109.28 4117.6,2096.84 4105.16,2121.72 4117.6,2146.61 4092.72,2134.17 4067.83,2146.61 4080.27,2121.72 4067.83,2096.84 ; 4067.83,2258.6 4080.27,2258.6 4080.27,2246.16 4105.16,2246.16 4105.16,2258.6 4117.6,2258.6 4117.6,2283.49 4105.16,2283.49 4105.16,2295.93 4080.27,2295.93 4080.27,2283.49 4067.83,2283.49 4067.83,2258.6 ; 4077.78,1964.94 4085.25,1964.94 4092.72,1957.47 4100.18,1964.94 4107.65,1964.94 4100.18,1972.4 4107.65,1979.87 4100.18,1979.87 4092.72,1987.33 4085.25,1979.87 4077.78,1979.87 4085.25,1972.4 4077.78,1964.94 ; 4077.78,2263.58 4085.25,2263.58 4085.25,2256.11 4100.18,2256.11 4100.18,2263.58 4107.65,2263.58 4107.65,2278.51 4100.18,2278.51 4100.18,2285.97 4085.25,2285.97 4085.25,2278.51 4077.78,2278.51 4077.78,2263.58
  lines w12: 4000,1156.12 6118.02,1156.12 ; 4000,2350.68 6118.02,2350.68 ; 4370.36,1006.8 4370.36,2500 ; 4727.36,1006.8 4727.36,2500 ; 5388.93,1006.8 5388.93,2500 ; 5673.07,1006.8 5673.07,2500 ; 4000,1006.8 6118.02,1006.8 6118.02,2500 4000,2500 4000,1006.8
  text "Symbol" at 4089.59,2395.48 h72
  text "Quantity" at 4415.16,2395.48 h72
  text "Finished Hole Size" at 4772.16,2395.48 h72
  text "Plated" at 5433.72,2395.48 h72
  text "Hole Type" at 5717.86,2395.48 h72
  text "12" at 4415.16,2246.16 h60
  text "8.00mil (0.203mm)" at 4772.16,2246.16 h60
  text "PTH" at 5433.72,2246.16 h60
  text "Round" at 5717.86,2246.16 h60
  text "357" at 4415.16,2096.84 h60
  text "10.00mil (0.254mm)" at 4772.16,2096.84 h60
  text "PTH" at 5433.72,2096.84 h60
  text "Round" at 5717.86,2096.84 h60
  text "91" at 4415.16,1947.52 h60
  text "12.00mil (0.305mm)" at 4772.16,1947.52 h60
  text "PTH" at 5433.72,1947.52 h60
  text "Round" at 5717.86,1947.52 h60
  text "10" at 4415.16,1798.2 h60
  text "31.00mil (0.787mm)" at 4772.16,1798.2 h60
  text "PTH" at 5433.72,1798.2 h60
  text "Round" at 5717.86,1798.2 h60
  text "4" at 4415.16,1648.88 h60
  text "39.37mil (1.000mm)" at 4772.16,1648.88 h60
  text "PTH" at 5433.72,1648.88 h60
  text "Round" at 5717.86,1648.88 h60
  text "12" at 4415.16,1499.56 h60
  text "40.00mil (1.016mm)" at 4772.16,1499.56 h60
  text "PTH" at 5433.72,1499.56 h60
  text "Round" at 5717.86,1499.56 h60
  text "20" at 4415.16,1350.24 h60
  text "45.28mil (1.150mm)" at 4772.16,1350.24 h60
  text "PTH" at 5433.72,1350.24 h60
  text "Round" at 5717.86,1350.24 h60
  text "8" at 4415.16,1200.92 h60
  text "51.18mil (1.300mm)" at 4772.16,1200.92 h60
  text "PTH" at 5433.72,1200.92 h60
  text "Round" at 5717.86,1200.92 h60
  text "514 Total" at 4415.16,1051.6 h60
  text ".Layer_Name" at 577,-858.49 h60

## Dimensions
0,-400 to 1000,-400 on M2 Board Dimensions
